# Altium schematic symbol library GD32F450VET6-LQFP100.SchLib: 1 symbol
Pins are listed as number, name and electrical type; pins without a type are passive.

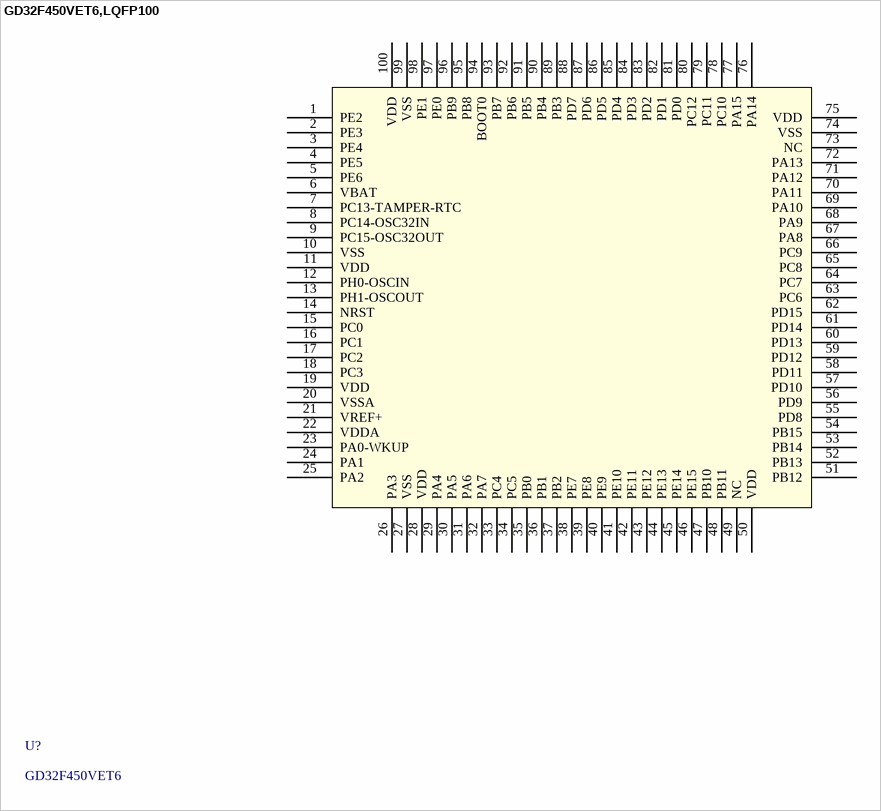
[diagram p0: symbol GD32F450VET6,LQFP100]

## GD32F450VET6,LQFP100
designator U?, comment GD32F450VET6
pins: 1 PE2, 2 PE3, 3 PE4, 4 PE5, 5 PE6, 6 VBAT, 7 PC13-TAMPER-RTC, 8 PC14-OSC32IN, 9 PC15-OSC32OUT, 10 VSS, 11 VDD, 12 PH0-OSCIN, 13 PH1-OSCOUT, 14 NRST, 15 PC0, 16 PC1, 17 PC2, 18 PC3, 19 VDD, 20 VSSA, 21 VREF+, 22 VDDA, 23 PA0-WKUP, 24 PA1, 25 PA2, 26 PA3, 27 VSS, 28 VDD, 29 PA4, 30 PA5, 31 PA6, 32 PA7, 33 PC4, 34 PC5, 35 PB0, 36 PB1, 37 PB2, 38 PE7, 39 PE8, 40 PE9, 41 PE10, 42 PE11, 43 PE12, 44 PE13, 45 PE14, 46 PE15, 47 PB10, 48 PB11, 49 NC, 50 VDD, 51 PB12, 52 PB13, 53 PB14, 54 PB15, 55 PD8, 56 PD9, 57 PD10, 58 PD11, 59 PD12, 60 PD13, 61 PD14, 62 PD15, 63 PC6, 64 PC7, 65 PC8, 66 PC9, 67 PA8, 68 PA9, 69 PA10, 70 PA11, 71 PA12, 72 PA13, 73 NC, 74 VSS, 75 VDD, 76 PA14, 77 PA15, 78 PC10, 79 PC11, 80 PC12, 81 PD0, 82 PD1, 83 PD2, 84 PD3, 85 PD4, 86 PD5, 87 PD6, 88 PD7, 89 PB3, 90 PB4, 91 PB5, 92 PB6, 93 PB7, 94 BOOT0, 95 PB8, 96 PB9, 97 PE0, 98 PE1, 99 VSS, 100 VDD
